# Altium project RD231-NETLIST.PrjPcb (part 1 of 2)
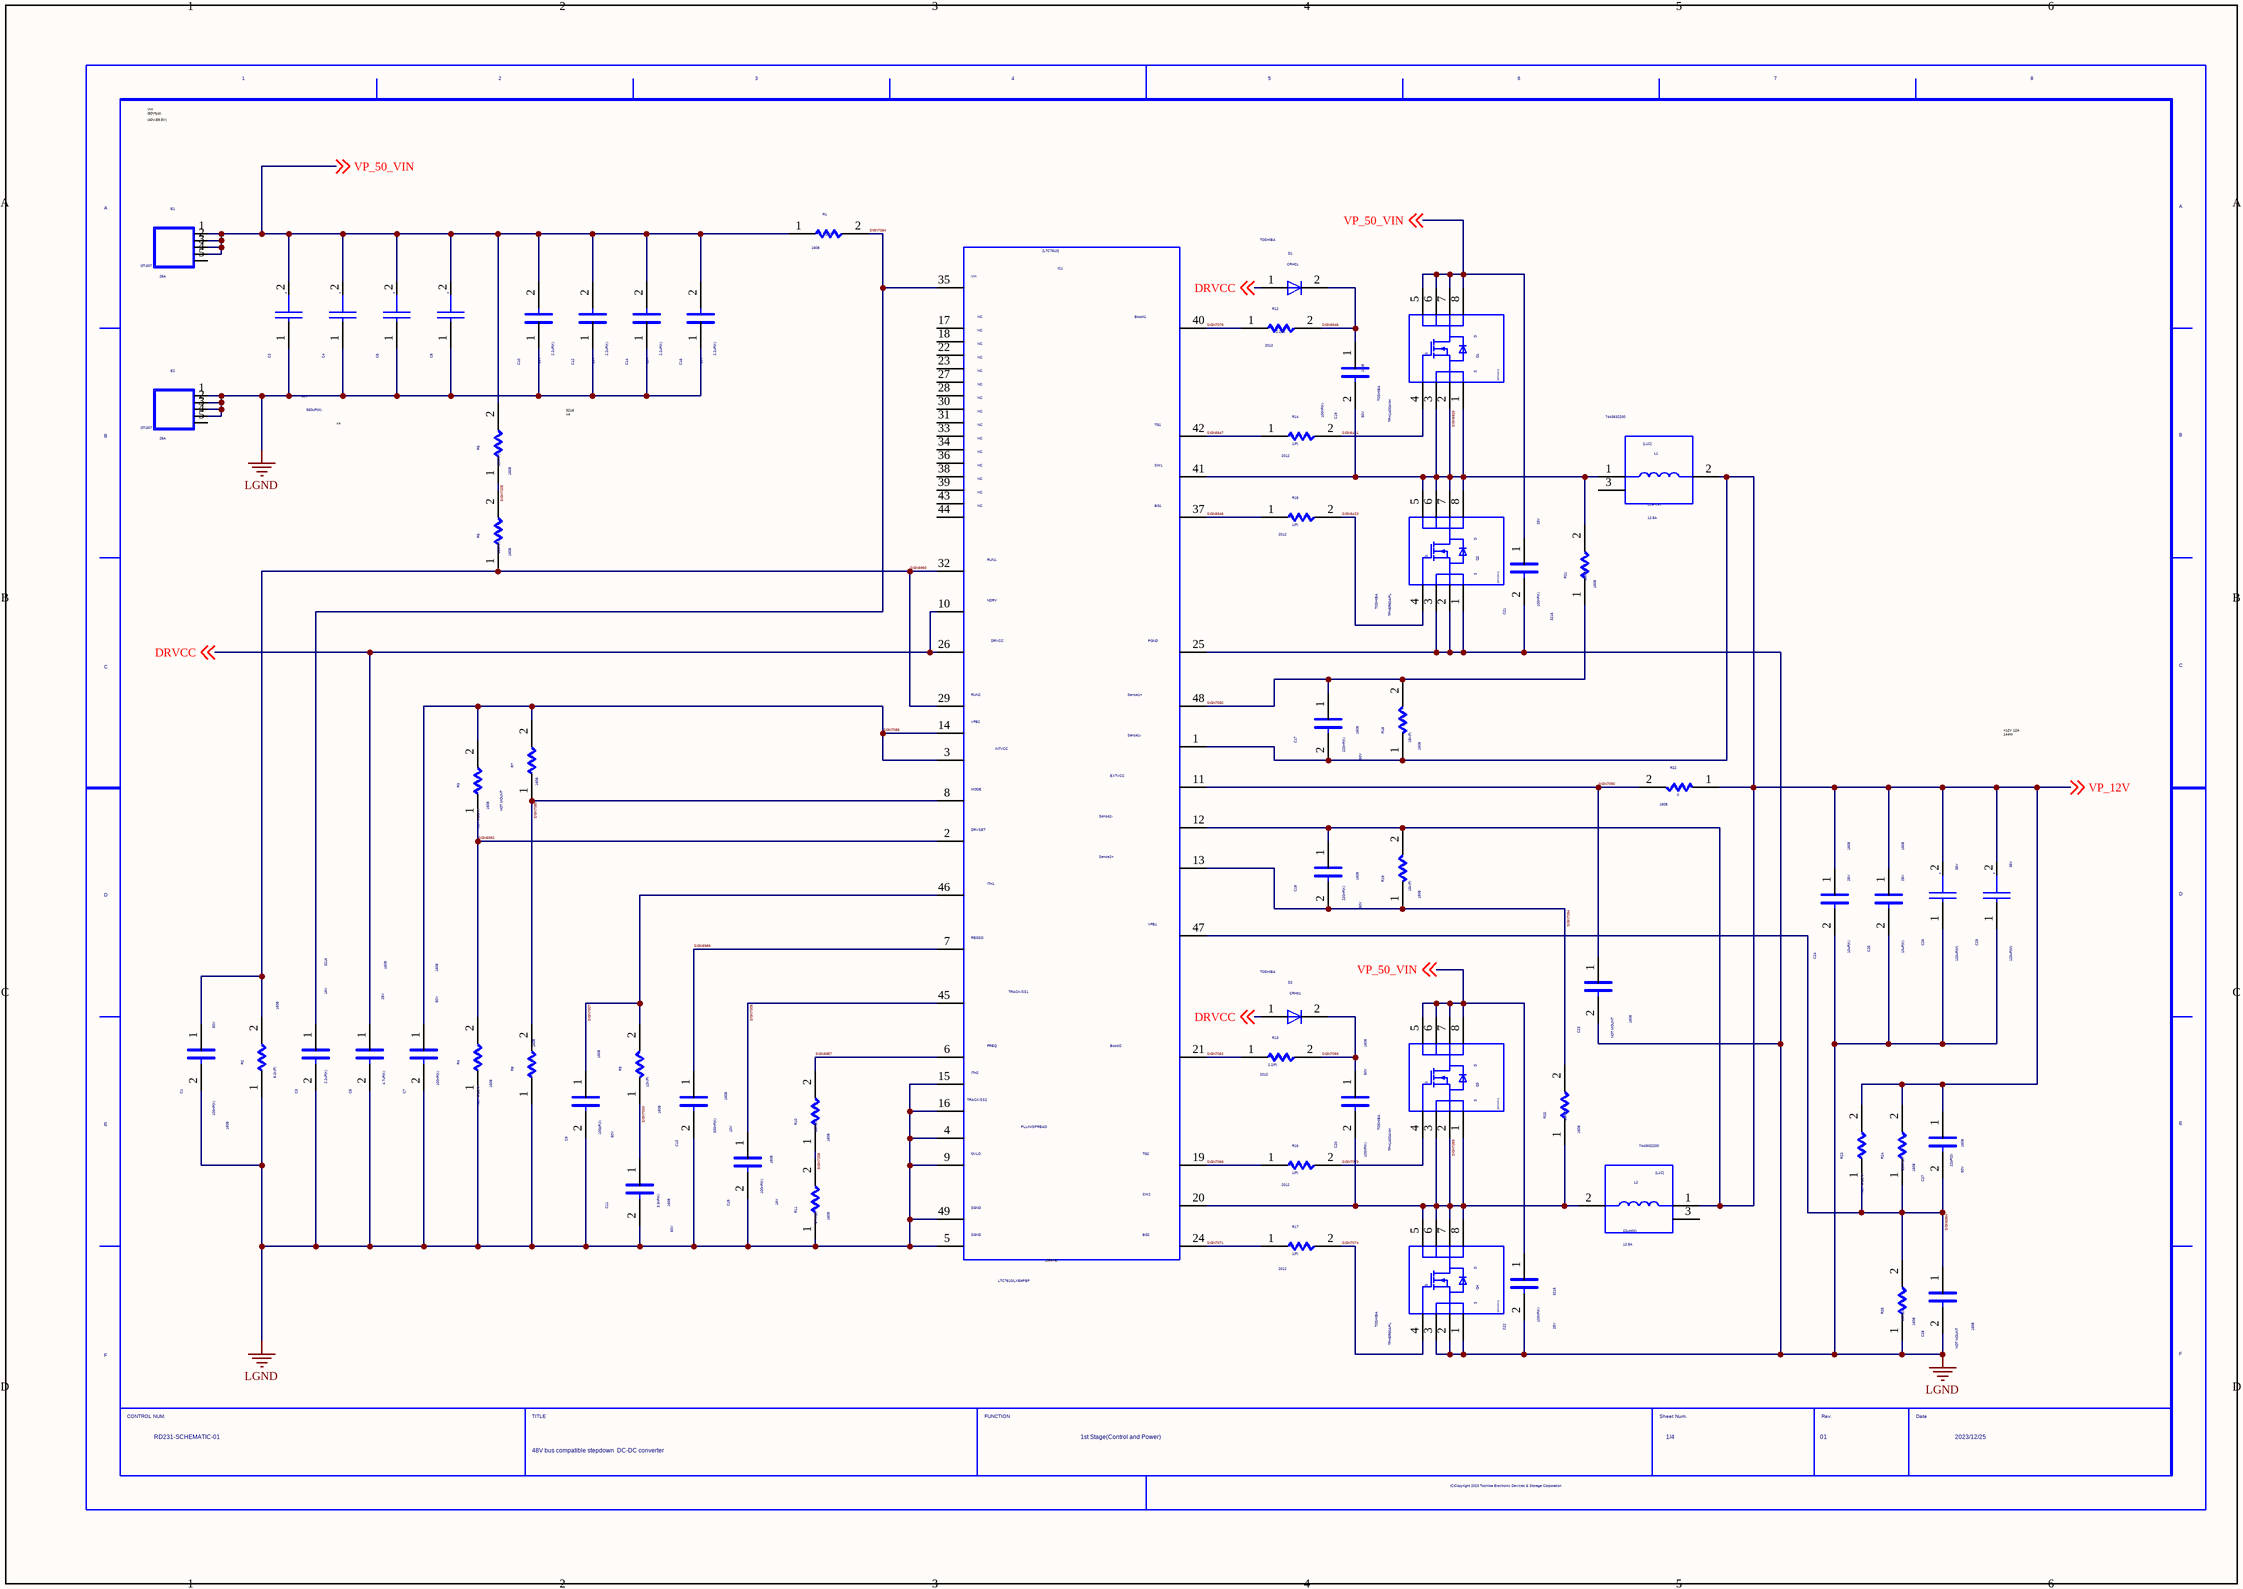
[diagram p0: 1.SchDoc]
4 sheets, 318 parts. Net scope: global (net labels, ports and power ports of the same name join across sheets).
Sheets:
  1.SchDoc
  2.SchDoc
  3.SchDoc
  4.SchDoc

## Sheet 1.SchDoc
size 420 x 297 mm

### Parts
(Parts that share a designator on the sheet are numbered #1, #2 ... from top to bottom, then left to right.)
C1  VAL1: 100nF(K)  VAL2: 50V  SIZECODESMD: 1608  (hidden comment: C)
C2  VAL1: 560uF(M)  VAL2: 80V  (hidden comment: CP)
C3  VAL1: 2.2uF(K)  VAL2: 16V  SIZECODESMD: 3216  (hidden comment: C)
C4  CP  (value not drawn)
C5  VAL1: 4.7uF(K)  VAL2: 25V  SIZECODESMD: 1608  (hidden comment: C)
C6  CP  (value not drawn)
C7  VAL1: 100nF(K)  VAL2: 50V  SIZECODESMD: 1608  (hidden comment: C)
C8  CP  (value not drawn)
C9  VAL1: 100pF(J)  VAL2: 50V  SIZECODESMD: 1608  (hidden comment: C)
C10  VAL1: 2.2uF(K)  VAL2: 16V  (hidden comment: C)
C11  VAL1: 3.3nF(K)  VAL2: 50V  SIZECODESMD: 1608  (hidden comment: C)
C12  VAL1: 2.2uF(K)  VAL2: 16V  (hidden comment: C)
C13  VAL1: 330nF(K)  VAL2: 10V  SIZECODESMD: 1608  (hidden comment: C)
C14  VAL1: 2.2uF(K)  VAL2: 16V  (hidden comment: C)
C15  VAL1: 100nF(K)  VAL2: 16V  SIZECODESMD: 1608  (hidden comment: C)
C16  VAL1: 2.2uF(K)  VAL2: 16V  (hidden comment: C)
C17  VAL1: 220nF(K)  VAL2: 50V  SIZECODESMD: 1608  (hidden comment: C)
C18  VAL1: 220nF(K)  VAL2: 50V  SIZECODESMD: 1608  (hidden comment: C)
C19  VAL1: 100nF(K)  VAL2: 50V  SIZECODESMD: 1608  (hidden comment: C)
C20  VAL1: 100nF(K)  VAL2: 50V  SIZECODESMD: 1608  (hidden comment: C)
C21  VAL1: 100nF(K)  VAL2: 25V  SIZECODESMD: 3216  (hidden comment: C)
C22  VAL1: 100nF(K)  VAL2: 25V  SIZECODESMD: 3216  (hidden comment: C)
C23  SIZECODESMD: 1608  NOTMOUNT: NOT MOUNT  (hidden comment: C)
C24  VAL1: 10uF(K)  VAL2: 25V  SIZECODESMD: 1608  (hidden comment: C)
C25  VAL1: 10uF(K)  VAL2: 25V  SIZECODESMD: 1608  (hidden comment: C)
C26  VAL1: 120uF(M)  VAL2: 35V  (hidden comment: CP)
C27  VAL1: 22pF(D)  VAL2: 50V  SIZECODESMD: 1608  (hidden comment: C)
C28  SIZECODESMD: 1608  NOTMOUNT: NOT MOUNT  (hidden comment: C)
C29  VAL1: 120uF(M)  VAL2: 35V  (hidden comment: CP)
D1  VAL3: CRH01  USERCOMPTEXT3: TOSHIBA  (hidden comment: D)
D2  VAL3: CRH01  USERCOMPTEXT3: TOSHIBA  (hidden comment: D)
E1  VAL1: 25A  VAL3: OT-007  (hidden comment: EB)
E2  VAL1: 25A  VAL3: OT-007  (hidden comment: EB)
IC1  VAL3: LTC7810ILXE#PBF  (hidden comment: LTC7810_1)
L1  VAL1: 22uH(M)  VAL2: 12.5A  VAL3: 7443632200  (hidden comment: L1C)
L2  VAL1: 22uH(M)  VAL2: 12.5A  VAL3: 7443632200  (hidden comment: L1C)
Q1  VAL3: TPH1400ANH  USERCOMPTEXT3: TOSHIBA  (hidden comment: MFNKR2)
Q2  VAL3: TPH5R60APL  USERCOMPTEXT3: TOSHIBA  (hidden comment: MFNKR2)
Q3  VAL3: TPH1400ANH  USERCOMPTEXT3: TOSHIBA  (hidden comment: MFNKR2)
Q4  VAL3: TPH5R60APL  USERCOMPTEXT3: TOSHIBA  (hidden comment: MFNKR2)
R1  VAL1: 2.2(F)  SIZECODESMD: 1608  (hidden comment: R)
R2  VAL1: 8.2k(F)  SIZECODESMD: 1608  (hidden comment: R)
R3  NOTMOUNT: NOT MOUNT  SIZECODESMD: 1608  (hidden comment: R)
R4  NOTMOUNT: NOT MOUNT  SIZECODESMD: 1608  (hidden comment: R)
R5  VAL1: 110k(F)  SIZECODESMD: 1608  (hidden comment: R)
R6  VAL1: 110k(F)  SIZECODESMD: 1608  (hidden comment: R)
R7  SIZECODESMD: 1608  NOTMOUNT: NOT MOUNT  (hidden comment: R)
R8  VAL1: 0  SIZECODESMD: 1608  (hidden comment: R)
R9  VAL1: 12k(F)  SIZECODESMD: 1608  (hidden comment: R)
R10  VAL1: 22k(D)  SIZECODESMD: 1608  (hidden comment: R)
R11  VAL1: 2.7k(D)  SIZECODESMD: 1608  (hidden comment: R)
R12  VAL1: 2.2(F)  SIZECODESMD: 2012  (hidden comment: R)
R13  VAL1: 2.2(F)  SIZECODESMD: 2012  (hidden comment: R)
R14  VAL1: 1(F)  SIZECODESMD: 2012  (hidden comment: R)
R15  VAL1: 1(F)  SIZECODESMD: 2012  (hidden comment: R)
R16  VAL1: 1(F)  SIZECODESMD: 2012  (hidden comment: R)
R17  VAL1: 1(F)  SIZECODESMD: 2012  (hidden comment: R)
R18  VAL1: 15k(F)  SIZECODESMD: 1608  (hidden comment: R)
R19  VAL1: 15k(F)  SIZECODESMD: 1608  (hidden comment: R)
R20  VAL1: 10k(F)  SIZECODESMD: 1608  (hidden comment: R)
R21  VAL1: 10k(F)  SIZECODESMD: 1608  (hidden comment: R)
R22  VAL1: 0  SIZECODESMD: 1608  (hidden comment: R)
R23  NOTMOUNT: NOT MOUNT  (hidden comment: R)
R24  VAL1: 220k(D)  SIZECODESMD: 1608  (hidden comment: R)
R25  VAL1: 20k(D)  SIZECODESMD: 1608  (hidden comment: R)
U?#1  DATE: 2023/12/25  FUNCTION: 1st Stage(Control and Power)  DRAWINGNUMBER: RD231-SCHEMATIC-01  SHEETNUMBER: 1/4  REVISION: 01  TITLE: 48V bus compatible stepdown / DC-DC converter  (hidden comment: WAKU_DEF100)

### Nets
LGND: C1.2 C2.1 C3.2 C4.1 C5.2 C6.1 C7.2 C8.1 C9.2 C10.1 C11.2 C12.1 C13.2 C14.1 C15.2 C16.1 C21.2 C22.2 C23.2 C24.2 C25.2 C26.1 C28.2 C29.1 E2.1 E2.2 E2.3 E2.4 IC1.4 IC1.5 IC1.9 IC1.15 IC1.16 IC1.25 IC1.49 Q2.1 Q2.2 Q2.3 Q4.1 Q4.2 Q4.3 R2.1 R4.1 R8.1 R11.1 R25.1
DRVCC: C5.1 D1.1(A) D2.1(A) IC1.10 IC1.26 ; off-sheet DRVCC
SIGN6423: Q2.4 R15.2
SIGN6441: Q1.4 R14.2
SIGN6926: C19.2 IC1.41 L1.1 Q1.1 Q1.2 Q1.3 Q2.5 Q2.6 Q2.7 Q2.8 R21.2
SIGN6946: IC1.37 R15.1
SIGN6947: IC1.42 R14.1
SIGN6948: C19.1 D1.2(C) R12.2
SIGN6954: C27.2 C28.1 IC1.47 R23.1 R24.1 R25.2
SIGN6957: IC1.6 R10.2
SIGN6960: C1.1 IC1.29 IC1.32 R2.2 R6.1
SIGN6989: C13.1 IC1.7
SIGN6992: IC1.2 R3.1 R4.2
SIGN7000: C11.1 R9.1
SIGN7005: C15.1 IC1.45
SIGN7007: C9.1 IC1.46 R9.2
SIGN7059: C20.2 IC1.20 L2.2 Q3.1 Q3.2 Q3.3 Q4.5 Q4.6 Q4.7 Q4.8 R20.1
SIGN7062: IC1.21 R13.1
SIGN7068: IC1.19 R16.1
SIGN7069: C20.1 D2.2(C) R13.2
SIGN7071: IC1.24 R17.1
SIGN7073: Q3.4 R16.2
SIGN7074: Q4.4 R17.2
SIGN7078: IC1.40 R12.1
SIGN7084: C3.1 IC1.35 R1.2
SIGN7088: C7.1 IC1.3 IC1.14 R3.2 R7.2
SIGN7089: IC1.8 R7.1 R8.2
SIGN7090: C23.1 IC1.11 R22.2
SIGN7092: C17.1 IC1.48 R18.2 R21.1
SIGN7094: C18.2 IC1.13 R19.1 R20.2
SIGN7205: R5.1 R6.2
SIGN7208: R10.1 R11.2
VP_12V: C17.2 C18.1 C24.1 C25.1 C26.2 C27.1 C29.2 IC1.1 IC1.12 L1.2 L2.1 R18.1 R19.2 R22.1 R23.2 R24.2 ; off-sheet VP_12V
VP_50_VIN: C2.2 C4.2 C6.2 C8.2 C10.2 C12.2 C14.2 C16.2 C21.1 C22.1 E1.1 E1.2 E1.3 E1.4 Q1.5 Q1.6 Q1.7 Q1.8 Q3.5 Q3.6 Q3.7 Q3.8 R1.1 R5.2 ; off-sheet VP_50_VIN

Not connected (* = marked no-connect by the designer): E1 5; E2 5; IC1 17 18 22 23 27 28 30 31 33 34 36 38 39 43 44; L1 3; L2 3

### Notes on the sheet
- (40V-59.5V)
- Vin
  (50Vtyp)
- x4
- 3216
  x4
- +12V 12A
  144W
- (near IC1) 100kHz

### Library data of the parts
C1 C7 C19 C20 C23 = C: PARTCOMMENT: 代表セル<KC0008> がフットプリントに登録されていません。; FNPARTSNAMEG: CHIP CERAMIC CAPACITOR (1608); OriginalSymbolOrigin: (2540,7620); FNCLASSCODEG: P03-03; PCODE: P03B000001KW; USEWITHSCHEMA: YES; MFMOUNTSYMBOLP: 80; FUNCN: GDM030001005; MFFORMINGDIVP: KC; MFPACKAGEMETHOP: S; MFSOLDERINGPROP: .; COMPONENTNAME: GDM030001005_package; GCOUNT: 1
C2 C26 C29 = CP: FNPARTSCODEG: C; FNPARTSNAMEG: CHIP ALUMINUM ELECTROLYTIC CAPACITOR; SAVEAREA0: -1450,-153,20294,13055; SAVECOUNT: 52; TIME: 15:02:55; UPDATEUSER: fukuda-y; UPDATETIME: 16:13:42; OriginalSymbolOrigin: (2540,10160); USEWITHSCHEMA: YES; FUNCN: G36030155199; GCOUNT: 1; COMPONENTNAME: G36030155199_package; FNCLASSCODEG: P03-01; PCODE: P03090017118; MFMOUNTSYMBOLP: 80; MFFORMINGDIVP: KD; MFPACKAGEMETHOP: S; MFSOLDERINGPROP: F
C3 = C: FNPARTSNAMEG: CHIP CERAMIC CAPACITOR (3216); OriginalSymbolOrigin: (2540,7620); FNCLASSCODEG: P03-03; PCODE: P03042997321; USEWITHSCHEMA: YES; MFMOUNTSYMBOLP: 90; FUNCN: G36030110013; MFFORMINGDIVP: KC; MFPACKAGEMETHOP: S; MFSOLDERINGPROP: .; COMPONENTNAME: G36030110013_package; GCOUNT: 1; TOLERANCE: K
C4 C6 C8 = CP: FNPARTSCODEG: C; FNPARTSNAMEG: CHIP ALUMINUM ELECTROLYTIC CAPACITOR; SAVEAREA0: -1450,-153,20294,13055; SAVECOUNT: 52; TIME: 15:02:55; UPDATEUSER: fukuda-y; UPDATETIME: 16:13:42; OriginalSymbolOrigin: (2540,10160); USEWITHSCHEMA: YES; FUNCN: G36030155199; GCOUNT: 1; COMPONENTNAME: G36030155199_package; VAL1: 560uF(M); VAL2: 80V; FNCLASSCODEG: P03-01; PCODE: P03090017118; MFMOUNTSYMBOLP: 80; MFFORMINGDIVP: KD; MFPACKAGEMETHOP: S; MFSOLDERINGPROP: F
C5 = C: PARTCOMMENT: 代表セル<KC0008> がフットプリントに登録されていません。; FNPARTSNAMEG: CHIP CERAMIC CAPACITOR (1608); OriginalSymbolOrigin: (2540,7620); FNCLASSCODEG: P03-03; PCODE: P03B000001NY; USEWITHSCHEMA: YES; MFMOUNTSYMBOLP: 80; FUNCN: GDM030001182; MFFORMINGDIVP: KC; MFPACKAGEMETHOP: S; MFSOLDERINGPROP: .; COMPONENTNAME: GDM030001182_package; GCOUNT: 1
C9 = C: FNPARTSNAMEG: CHIP CERAMIC CAPACITOR (1608); OriginalSymbolOrigin: (2540,7620); FNCLASSCODEG: P03-03; PCODE: P03039307126; USEWITHSCHEMA: YES; MFMOUNTSYMBOLP: 80; FUNCN: G36030011181; MFFORMINGDIVP: KC; MFPACKAGEMETHOP: S; MFSOLDERINGPROP: .; COMPONENTNAME: G36030011181_package; GCOUNT: 1; TOLERANCE: J
C10 C12 C14 C16 = C: FNPARTSNAMEG: CHIP CERAMIC CAPACITOR (3216); OriginalSymbolOrigin: (2540,7620); FNCLASSCODEG: P03-03; USEWITHSCHEMA: YES; FUNCN: G36030110013; SIZECODESMD: 3216; COMPONENTNAME: G36030110013_package; GCOUNT: 1; PCODE: P03042997321; MFMOUNTSYMBOLP: 90; MFFORMINGDIVP: KC; MFPACKAGEMETHOP: S; MFSOLDERINGPROP: .; TOLERANCE: K
C11 = C: FNPARTSNAMEG: CHIP CERAMIC CAPACITOR (1608); OriginalSymbolOrigin: (2540,7620); FNCLASSCODEG: P03-03; PCODE: P03039A11122; USEWITHSCHEMA: YES; MFMOUNTSYMBOLP: 80; FUNCN: G36030011075; MFFORMINGDIVP: KC; MFPACKAGEMETHOP: S; MFSOLDERINGPROP: .; COMPONENTNAME: G36030011075_package; GCOUNT: 1; TOLERANCE: K
C13 = C: FNPARTSNAMEG: CHIP CERAMIC CAPACITOR (1608); OriginalSymbolOrigin: (2540,7620); FNCLASSCODEG: P03-03; PCODE: P03039ABF120; USEWITHSCHEMA: YES; MFMOUNTSYMBOLP: 80; FUNCN: G36030104111; MFFORMINGDIVP: KC; MFPACKAGEMETHOP: S; MFSOLDERINGPROP: .; COMPONENTNAME: G36030104111_package; GCOUNT: 1
C15 = C: FNPARTSNAMEG: CHIP CERAMIC CAPACITOR (1608); OriginalSymbolOrigin: (2540,7620); FNCLASSCODEG: P03-03; PCODE: P03039996139; USEWITHSCHEMA: YES; MFMOUNTSYMBOLP: 80; FUNCN: G36030011419; MFFORMINGDIVP: KC; MFPACKAGEMETHOP: S; MFSOLDERINGPROP: .; COMPONENTNAME: G36030011419_package; GCOUNT: 1
C17 C18 = C: FNPARTSNAMEG: CHIP CERAMIC CAPACITOR (1608); OriginalSymbolOrigin: (2540,7620); FNCLASSCODEG: P03-03; PCODE: P03039ABG127; USEWITHSCHEMA: YES; MFMOUNTSYMBOLP: 80; FUNCN: G36030104128; MFFORMINGDIVP: KC; MFPACKAGEMETHOP: S; MFSOLDERINGPROP: .; COMPONENTNAME: G36030104128_package; GCOUNT: 1
C21 C22 = C: FNPARTSNAMEG: CHIP CERAMIC CAPACITOR (3216); OriginalSymbolOrigin: (2540,7620); FNCLASSCODEG: P03-03; PCODE: P03042006320; USEWITHSCHEMA: YES; MFMOUNTSYMBOLP: 90; FUNCN: G36030031080; MFFORMINGDIVP: KC; MFPACKAGEMETHOP: S; MFSOLDERINGPROP: .; COMPONENTNAME: G36030031080_package; GCOUNT: 1; TOLERANCE: K
C24 C25 = C: FNPARTSNAMEG: CHIP CERAMIC CAPACITOR (1608); OriginalSymbolOrigin: (2540,7620); FNCLASSCODEG: P03-03; PCODE: P03B000000MS; USEWITHSCHEMA: YES; MFMOUNTSYMBOLP: 80; FUNCN: GDM030000053; MFFORMINGDIVP: KC; MFPACKAGEMETHOP: S; MFSOLDERINGPROP: .; COMPONENTNAME: GDM030000053_package; GCOUNT: 1
C27 C28 = C: FNPARTSNAMEG: CHIP CERAMIC CAPACITOR (1608); OriginalSymbolOrigin: (2540,7620); FNCLASSCODEG: P03-03; PCODE: P03039185229; USEWITHSCHEMA: YES; MFMOUNTSYMBOLP: 80; FUNCN: G36030011013; MFFORMINGDIVP: KC; MFPACKAGEMETHOP: S; MFSOLDERINGPROP: .; COMPONENTNAME: G36030011013_package; GCOUNT: 1; TOLERANCE: D
D1 D2 = D: SAVEAREA0: -565,-171,12979,8058; SAVECOUNT: 3; TIME: 14:49:55; UPDATEUSER: 19870035; UPDATETIME: 14:20:16; OriginalSymbolOrigin: (5080,5080); USEWITHSCHEMA: YES; VAL1: 1A; OUMEMAKERKATAMEI: CMF02(TE12R,Q); COMP: 5P9L1110P002; OUMEMAKER: 東芝; VAL2: 200V
E1 E2 = EB: SAVEAREA0: -10166,-6669,19798,9727; TIME: 17:33:04; UPDATEUSER: sptcae13; SAVECOUNT: 1; OriginalSymbolOrigin: (0,8890); COMP: 5P9L1232P001
IC1 = LTC7810_1: TIME: 17:42:33; UPDATEUSER: q91873sr; UPDATETIME: 00:58:17; SAVECOUNT: 171; SAVEAREA0: -56936,59772,124648,157086; OriginalSymbolOrigin: (5080,193040); USEWITHSCHEMA: YES; COMPONENTNAME: LTC7810_1.LTC7810_1; GCOUNT: 1
L1 L2 = L1C: SAVECOUNT: 6; SAVEAREA0: -5636,-341,27978,18652; OriginalSymbolOrigin: (5080,15240); USEWITHSCHEMA: YES; OUMEMAKERKATAMEI: 7443630140; GCOUNT: 1; OUMEMAKER: WURTH; COMPONENTNAME: L1C_L1C
Q1-Q4 = MFNKR2: SAVEAREA0: -9199,-39,32138,22820; TIME: 18:57:44; UPDATEUSER: q91866sr; UPDATETIME: 12:36:02; SAVECOUNT: 10; OriginalSymbolOrigin: (5080,20320); USEWITHSCHEMA: YES; OUMEMAKERKATAMEI: TPH6R003NL; COMPONENTNAME: MFNKR2_MFNKR2; GCOUNT: 1
R1 = R: FNPARTSNAMEG: CHIP RESISTOR (1608); OriginalSymbolOrigin: (5080,5080); FNCLASSCODEG: P01-08; PCODE: P01183001112; USEWITHSCHEMA: YES; VAL2: 100mW; NUMBEROFELEMENT: 0; COMP: G36010141013; MFFORMINGDIVP: KC; MFPACKAGEMETHOP: S; MFSOLDERINGPROP: .; MFMOUNTSYMBOLP: 80; COMPONENTNAME: G36010141013_package
R2 = R: FNPARTSNAMEG: CHIP RESISTOR (1608); OriginalSymbolOrigin: (5080,5080); FNCLASSCODEG: P01-08; PCODE: P01042507328; USEWITHSCHEMA: YES; VAL2: 100mW; NUMBEROFELEMENT: 0; COMP: G36010027188; MFFORMINGDIVP: KC; MFPACKAGEMETHOP: S; MFSOLDERINGPROP: .; MFMOUNTSYMBOLP: 80; COMPONENTNAME: G36010027188_package; GCOUNT: 1; TOLERANCE: F
R3 R4 = R: FNPARTSNAMEG: CHIP RESISTOR (1608); OriginalSymbolOrigin: (5080,5080); FNCLASSCODEG: P01-08; PCODE: P01042049A26; USEWITHSCHEMA: YES; NUMBEROFELEMENT: 0; COMP: G36010027034; MFFORMINGDIVP: KC; MFPACKAGEMETHOP: S; MFSOLDERINGPROP: .; MFMOUNTSYMBOLP: 80; COMPONENTNAME: G36010027034_package; GCOUNT: 1; TOLERANCE: F
R5 R6 = R: FNPARTSNAMEG: CHIP RESISTOR (1608); OriginalSymbolOrigin: (5080,5080); FNCLASSCODEG: P01-08; PCODE: P01042519628; USEWITHSCHEMA: YES; VAL2: 100mW; NUMBEROFELEMENT: 0; COMP: G36010027300; MFFORMINGDIVP: KC; MFPACKAGEMETHOP: S; MFSOLDERINGPROP: .; MFMOUNTSYMBOLP: 80; COMPONENTNAME: G36010027300_package; GCOUNT: 1; TOLERANCE: F
R7 = R: FNPARTSNAMEG: CHIP RESISTOR (1608); OriginalSymbolOrigin: (5080,5080); FNCLASSCODEG: P01-08; PCODE: P01042045226; USEWITHSCHEMA: YES; NUMBEROFELEMENT: 0; COMP: G36010027133; MFFORMINGDIVP: KC; MFPACKAGEMETHOP: S; MFSOLDERINGPROP: .; MFMOUNTSYMBOLP: 80; COMPONENTNAME: G36010027133_package; GCOUNT: 1; TOLERANCE: F
R8 = R: FNPARTSNAMEG: CHIP RESISTOR (1608); OriginalSymbolOrigin: (5080,5080); FNCLASSCODEG: P01-08; PCODE: P01042207426; USEWITHSCHEMA: YES; COMP: G36010027089; MFFORMINGDIVP: KC; MFPACKAGEMETHOP: S; MFSOLDERINGPROP: .; MFMOUNTSYMBOLP: 80; COMPONENTNAME: G36010027089_package; GCOUNT: 1; TOLERANCE: F
R9 = R: FNPARTSNAMEG: CHIP RESISTOR (1608); OriginalSymbolOrigin: (5080,5080); FNCLASSCODEG: P01-08; USEWITHSCHEMA: YES; VAL2: 100mW; COMP: G36010027041; PCODE: P01042097423; NUMBEROFELEMENT: 0; MFMOUNTSYMBOLP: 80; MFFORMINGDIVP: KC; MFPACKAGEMETHOP: S; MFSOLDERINGPROP: .; TOLERANCE: F; COMPONENTNAME: G36010027041_package; GCOUNT: 1
R10 = R: FNPARTSNAMEG: CHIP RESISTOR (1608); OriginalSymbolOrigin: (5080,5080); FNCLASSCODEG: P01-08; USEWITHSCHEMA: YES; VAL2: 62.5mW; COMP: G36010129578; PCODE: P01119059118; NUMBEROFELEMENT: 0; MFMOUNTSYMBOLP: 80; MFFORMINGDIVP: KC; MFPACKAGEMETHOP: S; MFSOLDERINGPROP: .; COMPONENTNAME: G36010129578_package; GCOUNT: 1
R11 = R: FNPARTSNAMEG: CHIP RESISTOR (1608); OriginalSymbolOrigin: (5080,5080); FNCLASSCODEG: P01-08; USEWITHSCHEMA: YES; VAL2: 62.5mW; COMP: G36010129356; PCODE: P01117039112; NUMBEROFELEMENT: 0; MFMOUNTSYMBOLP: 80; MFFORMINGDIVP: KC; MFPACKAGEMETHOP: S; MFSOLDERINGPROP: .; COMPONENTNAME: G36010129356_package; GCOUNT: 1
R12 R13 = R: FNPARTSNAMEG: CHIP RESISTOR (2012); OriginalSymbolOrigin: (5080,5080); FNCLASSCODEG: P01-08; PCODE: P01048019214; USEWITHSCHEMA: YES; VAL2: 125mW; NUMBEROFELEMENT: 0; MFMOUNTSYMBOLP: 90; FUNCN: G36010106012; MFFORMINGDIVP: KC; MFPACKAGEMETHOP: S; MFSOLDERINGPROP: .; COMPONENTNAME: G36010106012_package; GCOUNT: 1
R14-R17 = R: FNPARTSNAMEG: CHIP RESISTOR (2012); OriginalSymbolOrigin: (5080,5080); FNCLASSCODEG: P01-08; PCODE: P01048017210; USEWITHSCHEMA: YES; VAL2: 125mW; NUMBEROFELEMENT: 0; MFMOUNTSYMBOLP: 90; FUNCN: G36010106081; MFFORMINGDIVP: KC; MFPACKAGEMETHOP: S; MFSOLDERINGPROP: .; COMPONENTNAME: G36010106081_package; GCOUNT: 1
R18 R19 = R: FNPARTSNAMEG: CHIP RESISTOR (1608); OriginalSymbolOrigin: (5080,5080); FNCLASSCODEG: P01-08; USEWITHSCHEMA: YES; VAL2: 100mW; COMP: G36010027058; PCODE: P01042113727; NUMBEROFELEMENT: 0; MFMOUNTSYMBOLP: 80; MFFORMINGDIVP: KC; MFPACKAGEMETHOP: S; MFSOLDERINGPROP: .; TOLERANCE: F; COMPONENTNAME: G36010027058_package; GCOUNT: 1
R20 R21 = R: FNPARTSNAMEG: CHIP RESISTOR (1608); OriginalSymbolOrigin: (5080,5080); FNCLASSCODEG: P01-08; USEWITHSCHEMA: YES; VAL2: 100mW; COMP: G5101105R107; PCODE: P01042424625; NUMBEROFELEMENT: 0; MFMOUNTSYMBOLP: 80; MFFORMINGDIVP: KC; MFPACKAGEMETHOP: S; MFSOLDERINGPROP: .; COMPONENTNAME: G5101105R107_package; GCOUNT: 1
R22 = R: PARTCOMMENT: 代表セル<KC0008> がフットプリントに登録されていません。; FNPARTSNAMEG: CHIP JUMPER 1608TYPE; OriginalSymbolOrigin: (5080,5080); FNCLASSCODEG: P01-08; USEWITHSCHEMA: YES; FUNCN: K0100346; COMPONENTNAME: K0100346_package; GCOUNT: 1
R23 = R: FNPARTSNAMEG: CHIP RESISTOR (1608); OriginalSymbolOrigin: (5080,5080); FNCLASSCODEG: P01-08; USEWITHSCHEMA: YES; COMP: G5101106F106; PCODE: P01042680229; NUMBEROFELEMENT: 0; MFMOUNTSYMBOLP: 80; MFFORMINGDIVP: KC; MFPACKAGEMETHOP: S; MFSOLDERINGPROP: .; COMPONENTNAME: G5101106F106_package; GCOUNT: 1; SIZECODESMD: 1608
R24 = R: FNPARTSNAMEG: CHIP RESISTOR (1608); OriginalSymbolOrigin: (5080,5080); FNCLASSCODEG: P01-08; USEWITHSCHEMA: YES; VAL2: 62.5mW; COMP: G5101109J104; PCODE: P01042669620; NUMBEROFELEMENT: 0; MFMOUNTSYMBOLP: 80; MFFORMINGDIVP: KC; MFPACKAGEMETHOP: S; MFSOLDERINGPROP: .; COMPONENTNAME: G5101109J104_package; GCOUNT: 1
R25 = R: FNPARTSNAMEG: CHIP RESISTOR (1608); OriginalSymbolOrigin: (5080,5080); FNCLASSCODEG: P01-08; USEWITHSCHEMA: YES; VAL2: 62.5mW; COMP: G36010129493; PCODE: P01117053118; NUMBEROFELEMENT: 0; MFMOUNTSYMBOLP: 80; MFFORMINGDIVP: KC; MFPACKAGEMETHOP: S; MFSOLDERINGPROP: .; COMPONENTNAME: G36010129493_package; GCOUNT: 1
U?#1 = WAKU_DEF100: PLOTTIME: HH:MM; SAVEAREA0: -56280,0,471144,298016; TIME: 20:22:11; UPDATEUSER: sptcae13; UPDATETIME: 11:34:32; SAVECOUNT: 8; OriginalSymbolOrigin: (10160,284480)

## Sheet 2.SchDoc
size 420 x 297 mm
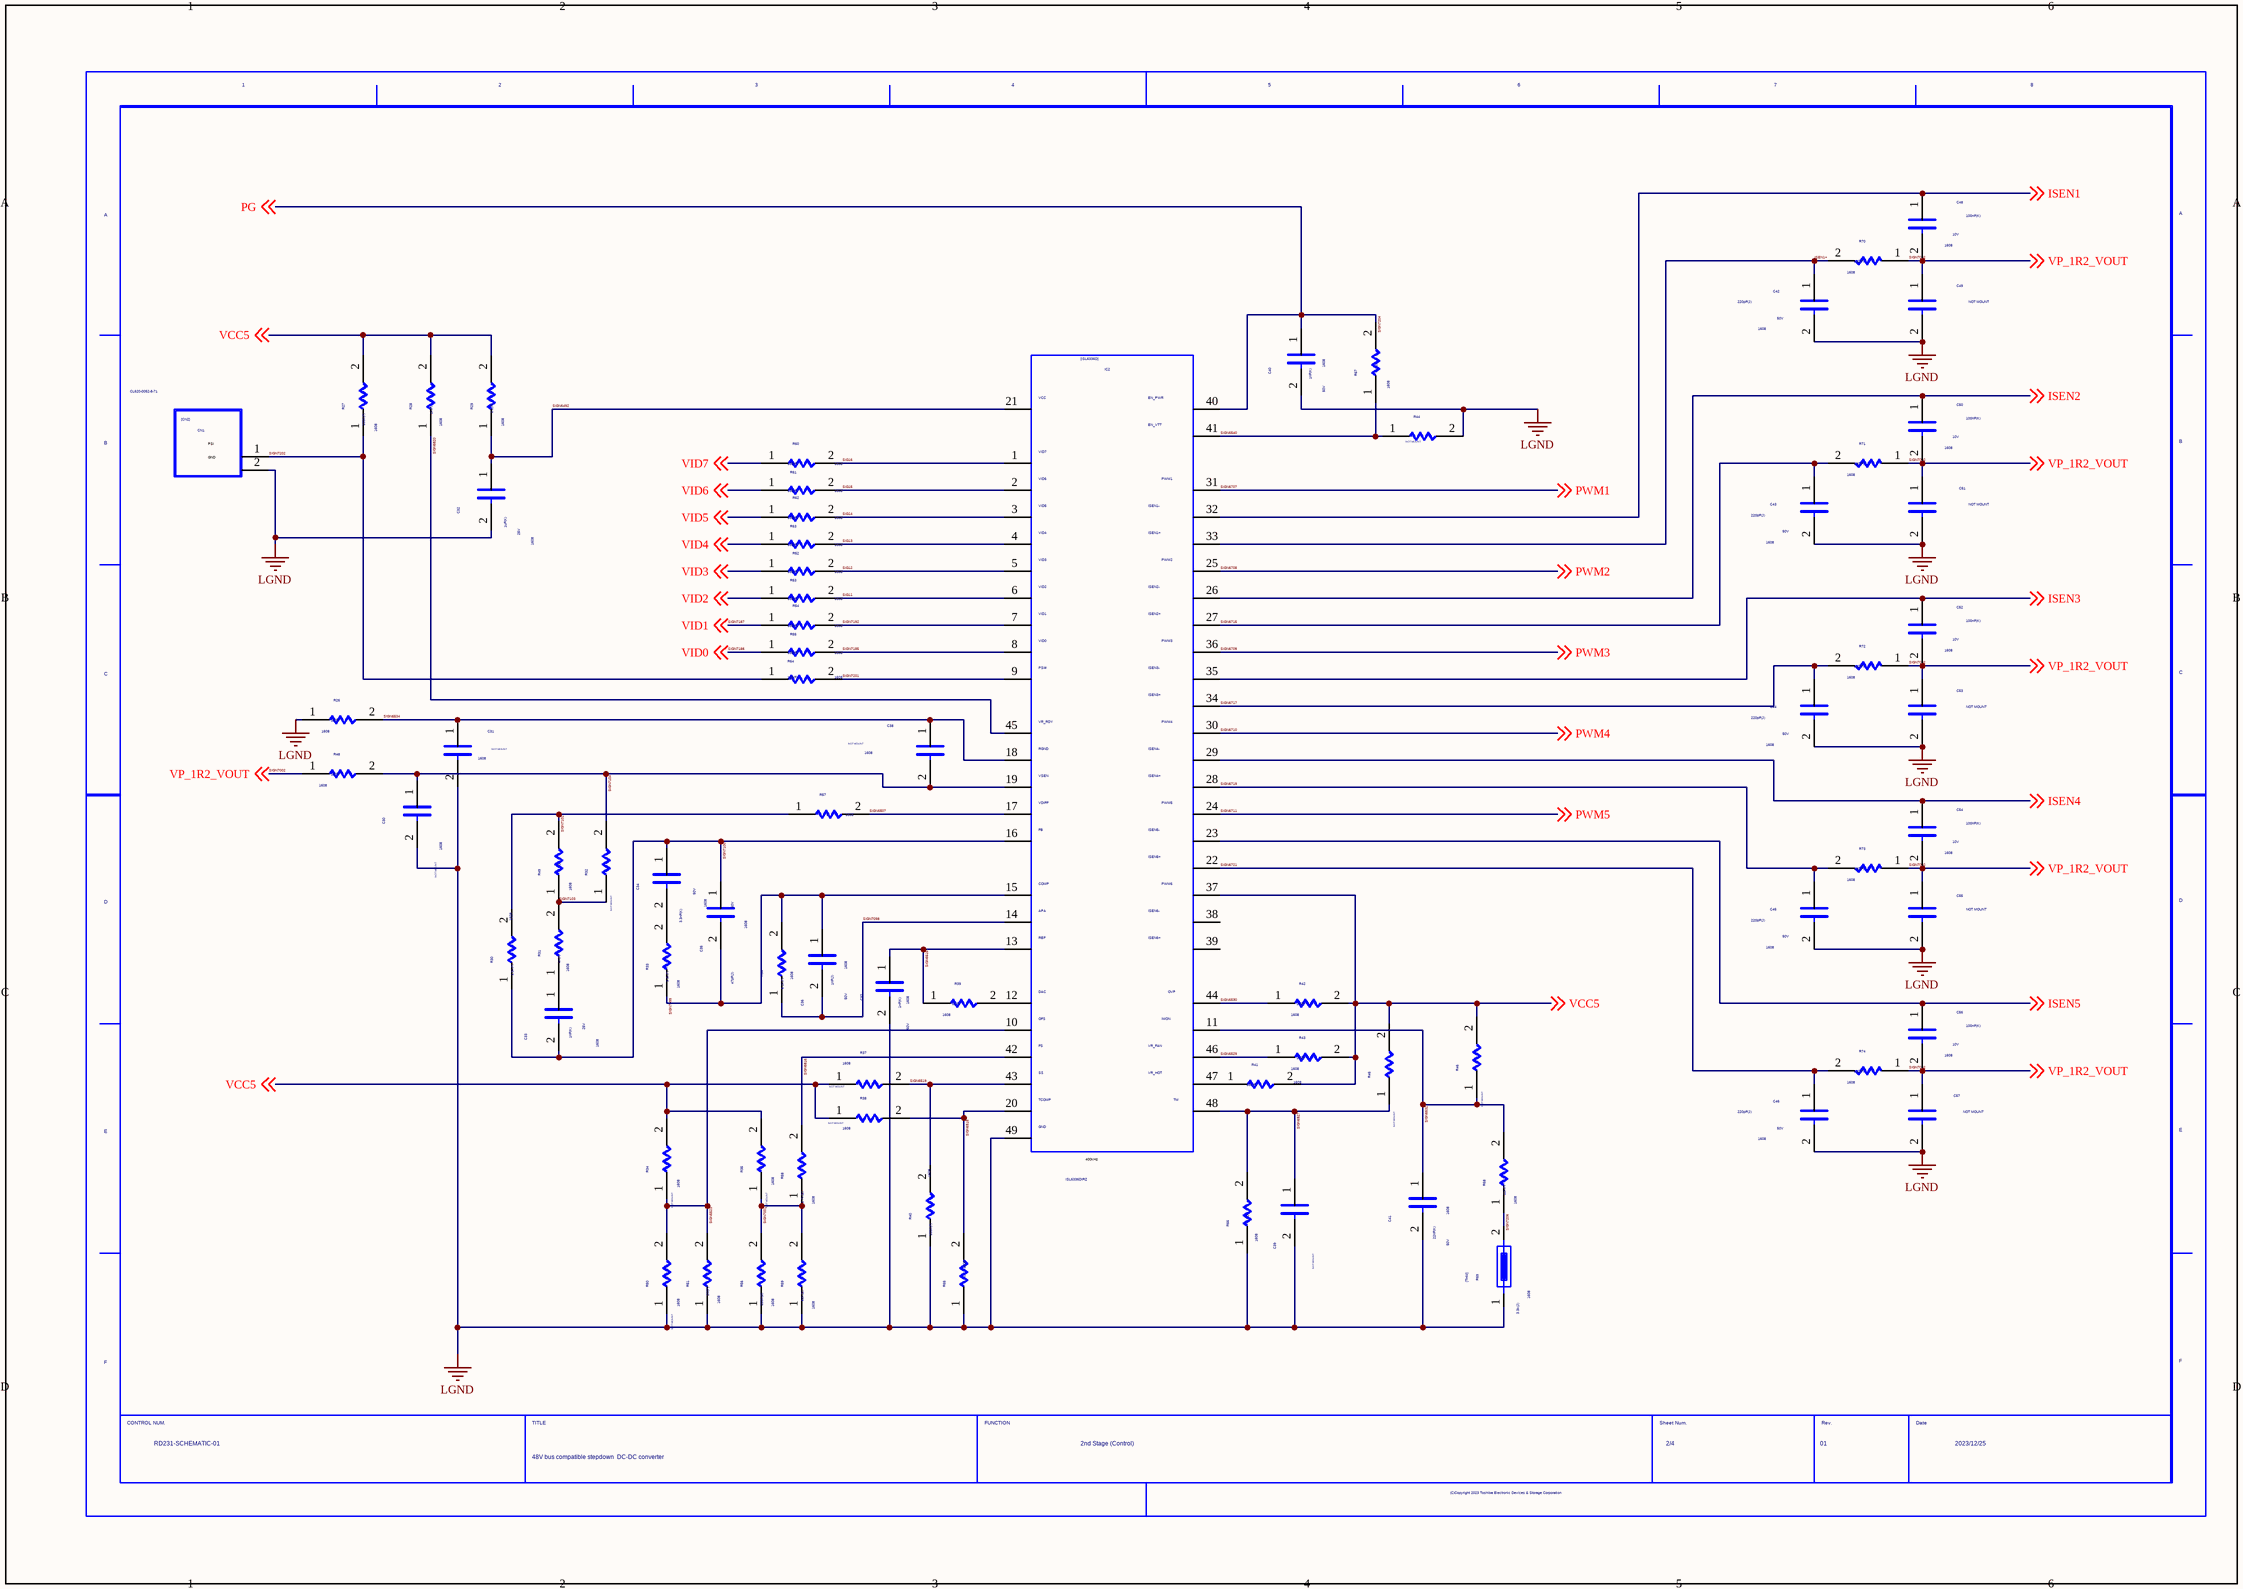
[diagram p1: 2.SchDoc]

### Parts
(Parts that share a designator on the sheet are numbered #1, #2 ... from top to bottom, then left to right.)
C30  NOTMOUNT: NOT MOUNT  SIZECODESMD: 1608  (hidden comment: C)
C31  NOTMOUNT: NOT MOUNT  SIZECODESMD: 1608  (hidden comment: C)
C32  SIZECODESMD: 1608  VAL2: 25V  VAL1: 1uF(K)  (hidden comment: C)
C33  SIZECODESMD: 1608  VAL2: 25V  VAL1: 1nF(K)  (hidden comment: C)
C34  SIZECODESMD: 1608  VAL2: 50V  VAL1: 3.3nF(K)  (hidden comment: C)
C35  SIZECODESMD: 1608  VAL2: 50V  VAL1: 47pF(J)  (hidden comment: C)
C36  SIZECODESMD: 1608  VAL2: 50V  VAL1: 1nF(J)  (hidden comment: C)
C37  SIZECODESMD: 1608  VAL2: 50V  VAL1: 1nF(K)  (hidden comment: C)
C38  NOTMOUNT: NOT MOUNT  SIZECODESMD: 1608  (hidden comment: C)
C39  NOTMOUNT: NOT MOUNT  (hidden comment: C)
C40  SIZECODESMD: 1608  VAL2: 50V  VAL1: 1nF(K)  (hidden comment: C)
C41  SIZECODESMD: 1608  VAL2: 50V  VAL1: 22nF(K)  (hidden comment: C)
C42  SIZECODESMD: 1608  VAL2: 50V  VAL1: 220pF(J)  (hidden comment: C)
C43  SIZECODESMD: 1608  VAL2: 50V  VAL1: 220pF(J)  (hidden comment: C)
C44  SIZECODESMD: 1608  VAL2: 50V  VAL1: 220pF(J)  (hidden comment: C)
C45  SIZECODESMD: 1608  VAL2: 50V  VAL1: 220pF(J)  (hidden comment: C)
C46  SIZECODESMD: 1608  VAL2: 50V  VAL1: 220pF(J)  (hidden comment: C)
C48  SIZECODESMD: 1608  VAL2: 10V  VAL1: 100nF(K)  (hidden comment: C)
C49  NOTMOUNT: NOT MOUNT  (hidden comment: C)
C50  SIZECODESMD: 1608  VAL2: 10V  VAL1: 100nF(K)  (hidden comment: C)
C51  NOTMOUNT: NOT MOUNT  (hidden comment: C)
C52  SIZECODESMD: 1608  VAL2: 10V  VAL1: 100nF(K)  (hidden comment: C)
C53  NOTMOUNT: NOT MOUNT  (hidden comment: C)
C54  SIZECODESMD: 1608  VAL2: 10V  VAL1: 100nF(K)  (hidden comment: C)
C55  NOTMOUNT: NOT MOUNT  (hidden comment: C)
C56  SIZECODESMD: 1608  VAL2: 10V  VAL1: 100nF(K)  (hidden comment: C)
C57  NOTMOUNT: NOT MOUNT  (hidden comment: C)
CN1  VAL3: CL620-0052-8-71  (hidden comment: CN2)
IC2  VAL3: ISL6336DIRZ  (hidden comment: ISL6336D)
R26  SIZECODESMD: 1608  VAL1: 10(F)  (hidden comment: R)
R27  SIZECODESMD: 1608  VAL1: 100k(F)  (hidden comment: R)
R28  SIZECODESMD: 1608  VAL1: 1k(F)  (hidden comment: R)
R29  SIZECODESMD: 1608  VAL1: 2.2(F)  (hidden comment: R)
R30  SIZECODESMD: 1608  VAL1: 1.5k(F)  (hidden comment: R)
R31  SIZECODESMD: 1608  VAL1: 47(F)  (hidden comment: R)
R32  NOTMOUNT: NOT MOUNT  (hidden comment: R)
R33  SIZECODESMD: 1608  VAL1: 3.3k(F)  (hidden comment: R)
R34  SIZECODESMD: 1608  NOTMOUNT: NOT MOUNT  (hidden comment: R)
R35  SIZECODESMD: 1608  NOTMOUNT: NOT MOUNT  (hidden comment: R)
R36  SIZECODESMD: 1608  VAL1: 8.2k(F)  (hidden comment: R)
R37  SIZECODESMD: 1608  NOTMOUNT: NOT MOUNT  (hidden comment: R)
R38  SIZECODESMD: 1608  NOTMOUNT: NOT MOUNT  (hidden comment: R)
R39  SIZECODESMD: 1608  VAL1: 1k(F)  (hidden comment: R)
R40  SIZECODESMD: 1608  VAL1: 100k(F)  (hidden comment: R)
R41  SIZECODESMD: 1608  VAL1: 10k(F)  (hidden comment: R)
R42  SIZECODESMD: 1608  VAL1: 1k(F)  (hidden comment: R)
R43  SIZECODESMD: 1608  VAL1: 1k(F)  (hidden comment: R)
R44  NOTMOUNT: NOT MOUNT  (hidden comment: R)
R45  NOTMOUNT: NOT MOUNT  (hidden comment: R)
R46  NOTMOUNT: NOT MOUNT  (hidden comment: R)
R48  SIZECODESMD: 1608  VAL1: 10(F)  (hidden comment: R)
R49  SIZECODESMD: 1608  VAL1: 0  (hidden comment: R)
R50  SIZECODESMD: 1608  NOTMOUNT: NOT MOUNT  (hidden comment: R)
R51  SIZECODESMD: 1608  VAL1: 1M(F)  (hidden comment: R)
R52  SIZECODESMD: 1608  VAL1: 100(F)  (hidden comment: R)
R53  SIZECODESMD: 1608  VAL1: 100(F)  (hidden comment: R)
R54  SIZECODESMD: 1608  VAL1: 100(F)  (hidden comment: R)
R55  SIZECODESMD: 1608  VAL1: 100(F)  (hidden comment: R)
R56  SIZECODESMD: 1608  VAL1: 220k(D)  (hidden comment: R)
R57  SIZECODESMD: 1608  VAL1: 0  (hidden comment: R)
R58  SIZECODESMD: 1608  VAL1: 2.7k(D)  (hidden comment: R)
R59  SIZECODESMD: 1608  VAL1: 82k(D)  (hidden comment: R)
R60  SIZECODESMD: 1608  VAL1: 100(F)  (hidden comment: R)
R61  SIZECODESMD: 1608  VAL1: 100(F)  (hidden comment: R)
R62  SIZECODESMD: 1608  VAL1: 100(F)  (hidden comment: R)
R63  SIZECODESMD: 1608  VAL1: 100(F)  (hidden comment: R)
R64  SIZECODESMD: 1608  VAL1: 100(F)  (hidden comment: R)
R65  SIZECODESMD: 1608  VAL1: 0  (hidden comment: R)
R66  SIZECODESMD: 1608  VAL1: 0  (hidden comment: R)
R67  SIZECODESMD: 1608  VAL1: 0  (hidden comment: R)
R68  SIZECODESMD: 1608  VAL1: 11k(F)  (hidden comment: R)
R69  SIZECODESMD: 1608  VAL1: 3.3k(J)  (hidden comment: THM)
R70  SIZECODESMD: 1608  VAL1: 130(F)  (hidden comment: R)
R71  SIZECODESMD: 1608  VAL1: 130(F)  (hidden comment: R)
R72  SIZECODESMD: 1608  VAL1: 130(F)  (hidden comment: R)
R73  SIZECODESMD: 1608  VAL1: 130(F)  (hidden comment: R)
R74  SIZECODESMD: 1608  VAL1: 130(F)  (hidden comment: R)
U?#2  DATE: 2023/12/25  TITLE: 48V bus compatible stepdown / DC-DC converter  REVISION: 01  SHEETNUMBER: 2/4  DRAWINGNUMBER: RD231-SCHEMATIC-01  FUNCTION: 2nd Stage (Control)  (hidden comment: WAKU_DEF100)

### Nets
LGND: C30.2 C31.2 C32.2 C37.2 C39.2 C40.2 C41.2 C42.2 C43.2 C44.2 C45.2 C46.2 C49.2 C51.2 C53.2 C55.2 C57.2 CN1.2 IC2.49 R26.1 R40.1 R44.2 R50.1 R51.1 R56.1 R59.1 R65.1 R66.1 R69.1
ISEN1: C48.1 IC2.32 ; off-sheet ISEN1
ISEN1+: C42.1 IC2.33 R70.2
ISEN2: C50.1 IC2.26 ; off-sheet ISEN2
ISEN3: C52.1 IC2.35 ; off-sheet ISEN3
ISEN4: C54.1 IC2.29 ; off-sheet ISEN4
ISEN5: C56.1 IC2.23 ; off-sheet ISEN5
SIG11: IC2.6 R53.2
SIG12: IC2.5 R52.2
SIG13: IC2.4 R63.2
SIG14: IC2.3 R62.2
SIG15: IC2.2 R61.2
SIG16: IC2.1 R60.2
SIGN6492: C32.1 IC2.21 R29.1
SIGN6507: IC2.17 R57.2
SIGN6515: C37.1 IC2.13 R39.1
SIGN6516: IC2.20 R38.2 R65.2
SIGN6519: IC2.43 R37.2 R40.2
SIGN6523: IC2.10 R34.1 R50.2 R51.2
SIGN6527: C39.1 IC2.48 R45.1 R66.2
SIGN6529: IC2.46 R43.1
SIGN6530: IC2.44 R42.1
SIGN6532: C41.1 IC2.11 R46.1 R68.2
SIGN6534: C31.1 C38.1 IC2.18 R26.2
SIGN6540: IC2.41 R44.1 R67.1
SIGN6707: IC2.31 ; off-sheet PWM1  [also labelled PWM1]
SIGN6708: IC2.25 ; off-sheet PWM2  [also labelled PWM2]
SIGN6709: IC2.36 ; off-sheet PWM3  [also labelled PWM3]
SIGN6710: IC2.30 ; off-sheet PWM4  [also labelled PWM4]
SIGN6711: IC2.24 ; off-sheet PWM5  [also labelled PWM5]
SIGN6715: C43.1 IC2.27 R71.2
SIGN6717: C44.1 IC2.34 R72.2
SIGN6719: C45.1 IC2.28 R73.2
SIGN6721: C46.1 IC2.22 R74.2
SIGN6816: IC2.42 R58.2
SIGN6820: IC2.45 R28.1
SIGN7001: R35.1 R56.2 R58.1 R59.2
SIGN7002: C48.2 C49.1 C50.2 C51.1 C52.2 C53.1 C54.2 C55.1 C56.2 C57.1 R48.1 R70.1 R71.1 R72.1 R73.1 R74.1 ; off-sheet VP_1R2_VOUT  [also labelled VP_1R2_VOUT]
SIGN7098: C36.2 IC2.14 R36.1
SIGN7099: C35.2 C36.1 IC2.15 R33.1 R36.2
SIGN7100: C33.2 C34.1 C35.1 IC2.16 R30.1
SIGN7102: R30.2 R49.2 R57.1
SIGN7103: R31.2 R32.1 R49.1
SIGN7104: C30.1 C38.2 IC2.19 R32.2 R48.2
SIGN7185: IC2.8 R55.2
SIGN7186: R55.1 ; off-sheet VID0  [also labelled VID0]
SIGN7187: R54.1 ; off-sheet VID1  [also labelled VID1]
SIGN7192: IC2.7 R54.2
SIGN7201: IC2.9 R64.2
SIGN7202: CN1.1 R27.1 R64.1
SIGN7204: C40.1 IC2.40 R67.2 ; off-sheet PG  [also labelled PG]
SIGN7206: R68.1 R69.2
VCC5: IC2.37 R27.2 R28.2 R29.2 R34.2 R35.2 R37.1 R38.1 R41.2 R42.2 R43.2 R45.2 R46.2 ; off-sheet VCC5
VID2: R53.1 ; off-sheet VID2
VID3: R52.1 ; off-sheet VID3
VID4: R63.1 ; off-sheet VID4
VID5: R62.1 ; off-sheet VID5
VID6: R61.1 ; off-sheet VID6
VID7: R60.1 ; off-sheet VID7
NetC33_1: C33.1 R31.1
NetC34_2: C34.2 R33.2
NetIC2_12: IC2.12 R39.2
NetIC2_47: IC2.47 R41.1

Not connected (* = marked no-connect by the designer): IC2 38 39

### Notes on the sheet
- (near CN1) PSI
- (near CN1) GND
- (near IC2) 400kHz

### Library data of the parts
C30 C31 C38 = C: FNPARTSNAMEG: CHIP CERAMIC CAPACITOR (1608); USEINPARTSLIST: YES; OriginalSymbolOrigin: (2540,7620); TOLERANCE: K; MAXGCOUNT: 1; COMPONENTNAME: G36030011310_package; MFSOLDERINGPROP: .; MFPACKAGEMETHOP: S; MFFORMINGDIVP: KC; COMP: G36030011310; MFMOUNTSYMBOLP: 80; PCODE: P03039AAN526; FNCLASSCODEG: P03-03
C32 = C: FNPARTSNAMEG: CHIP CERAMIC CAPACITOR (1608); USEINPARTSLIST: YES; OriginalSymbolOrigin: (2540,7620); MAXGCOUNT: 1; COMPONENTNAME: G36030011433_package; MFSOLDERINGPROP: .; MFPACKAGEMETHOP: S; MFFORMINGDIVP: KC; COMP: G36030011433; MFMOUNTSYMBOLP: 80; PCODE: P03039992230; FNCLASSCODEG: P03-03
C33 = C: FNPARTSNAMEG: CHIP CERAMIC CAPACITOR (1608); USEINPARTSLIST: YES; OriginalSymbolOrigin: (2540,7620); TOLERANCE: K; MAXGCOUNT: 1; COMPONENTNAME: G36030011297_package; MFSOLDERINGPROP: .; MFPACKAGEMETHOP: S; MFFORMINGDIVP: KC; COMP: G36030011297; MFMOUNTSYMBOLP: 80; PCODE: P03039008221; FNCLASSCODEG: P03-03
C34 = C: FNPARTSNAMEG: CHIP CERAMIC CAPACITOR (1608); USEINPARTSLIST: YES; OriginalSymbolOrigin: (2540,7620); TOLERANCE: K; MAXGCOUNT: 1; COMPONENTNAME: G36030011037_package; MFSOLDERINGPROP: .; MFPACKAGEMETHOP: S; MFFORMINGDIVP: KC; COMP: G36030011037; MFMOUNTSYMBOLP: 80; PCODE: P03039A0T125; FNCLASSCODEG: P03-03
C35 = C: FNPARTSNAMEG: CHIP CERAMIC CAPACITOR (1608); USEINPARTSLIST: YES; OriginalSymbolOrigin: (2540,7620); TOLERANCE: K; MAXGCOUNT: 1; COMPONENTNAME: G36030011303_package; MFSOLDERINGPROP: .; MFPACKAGEMETHOP: S; MFFORMINGDIVP: KC; COMP: G36030011303; MFMOUNTSYMBOLP: 80; PCODE: P03039A0P127; FNCLASSCODEG: P03-03
C36 = C: FNPARTSNAMEG: CHIP CERAMIC CAPACITOR (1608); USEINPARTSLIST: YES; OriginalSymbolOrigin: (2540,7620); MAXGCOUNT: 1; COMPONENTNAME: G36030011747_package; MFSOLDERINGPROP: .; MFPACKAGEMETHOP: S; MFFORMINGDIVP: KC; COMP: G36030011747; MFMOUNTSYMBOLP: 80; PCODE: P03190012112; FNCLASSCODEG: P03-03
C37 C40 = C: FNPARTSNAMEG: CHIP CERAMIC CAPACITOR (1608); USEINPARTSLIST: YES; OriginalSymbolOrigin: (2540,7620); TOLERANCE: K; MAXGCOUNT: 1; COMPONENTNAME: G36030011044_package; MFSOLDERINGPROP: .; MFPACKAGEMETHOP: S; MFFORMINGDIVP: KC; COMP: G36030011044; MFMOUNTSYMBOLP: 80; PCODE: P03039045226; FNCLASSCODEG: P03-03
C39 = C: FNPARTSNAMEG: CHIP CERAMIC CAPACITOR (1608); USEINPARTSLIST: YES; OriginalSymbolOrigin: (2540,7620); TOLERANCE: K; MAXGCOUNT: 1; COMPONENTNAME: G36030011310_package; MFSOLDERINGPROP: .; MFPACKAGEMETHOP: S; MFFORMINGDIVP: KC; COMP: G36030011310; SIZECODESMD: 1608; MFMOUNTSYMBOLP: 80; PCODE: P03039AAN526; FNCLASSCODEG: P03-03
C41 = C: FNPARTSNAMEG: CHIP CERAMIC CAPACITOR (1608); USEINPARTSLIST: YES; OriginalSymbolOrigin: (2540,7620); TOLERANCE: K; PCODE: P03039008221; MAXGCOUNT: 1; COMPONENTNAME: G36030011297_package; MFSOLDERINGPROP: .; MFPACKAGEMETHOP: S; MFFORMINGDIVP: KC; COMP: G36030011297; MFMOUNTSYMBOLP: 80; FNCLASSCODEG: P03-03
C42-C46 = C: FNPARTSNAMEG: CHIP CERAMIC CAPACITOR (1608); USEINPARTSLIST: YES; OriginalSymbolOrigin: (2540,7620); MAXGCOUNT: 1; COMPONENTNAME: G36030011488_package; MFSOLDERINGPROP: .; MFPACKAGEMETHOP: S; MFFORMINGDIVP: KC; COMP: G36030011488; MFMOUNTSYMBOLP: 80; PCODE: P03039269127; FNCLASSCODEG: P03-03
C48 C50 C52 C54 C56 = C: FNPARTSNAMEG: CHIP CERAMIC CAPACITOR (1608); USEINPARTSLIST: YES; OriginalSymbolOrigin: (2540,7620); MAXGCOUNT: 1; COMPONENTNAME: GDM030000714_package; MFSOLDERINGPROP: .; MFPACKAGEMETHOP: S; MFFORMINGDIVP: KC; COMP: GDM030000714; MFMOUNTSYMBOLP: 80; PCODE: P03039ABE123; FNCLASSCODEG: P03-03
C49 C51 C53 C55 C57 = C: FNPARTSNAMEG: CHIP CERAMIC CAPACITOR (1608); USEINPARTSLIST: YES; OriginalSymbolOrigin: (2540,7620); MAXGCOUNT: 1; COMPONENTNAME: G36030104128_package; MFSOLDERINGPROP: .; MFPACKAGEMETHOP: S; MFFORMINGDIVP: KC; COMP: G36030104128; SIZECODESMD: 1608; MFMOUNTSYMBOLP: 80; PCODE: P03039ABG127; FNCLASSCODEG: P03-03
CN1 = CN2: USEINPARTSLIST: YES; OUMEPARTTYPE: PJ; OriginalSymbolOrigin: (2540,15240); MAXGCOUNT: 1; COMPONENTNAME: ZS_DPJ028_package; QUADMODEL: dummymodel; COMP: ZS_DPJ028
IC2 = ISL6336D: USEINPARTSLIST: YES; TIME: 17:42:33; UPDATEUSER: q91866sr; UPDATETIME: 10:56:10; SAVECOUNT: 140; SAVEAREA0: -131159,-2851,167371,162238; OriginalSymbolOrigin: (5080,152400); MAXGCOUNT: 1; COMPONENTNAME: ISL6336D.ISL6336D; OUMEMAKER: Renesas
R26 = R: FNPARTSNAMEG: CHIP RESISTOR (1608); USEINPARTSLIST: YES; OriginalSymbolOrigin: (5080,5080); COMPONENTNAME: G36010104063_package; FUNCN: G36010104063; TOLERANCE: F; MFSOLDERINGPROP: .; MFPACKAGEMETHOP: S; MFFORMINGDIVP: KC; MFMOUNTSYMBOLP: 80; NUMBEROFELEMENT: 0; PCODE: P01042036620; VAL2: 100mW; FNCLASSCODEG: P01-08
R27 = R: FNPARTSNAMEG: CHIP RESISTOR (1608); USEINPARTSLIST: YES; OriginalSymbolOrigin: (5080,5080); COMPONENTNAME: G36010027133_package; FUNCN: G36010027133; TOLERANCE: F; MFSOLDERINGPROP: .; MFPACKAGEMETHOP: S; MFFORMINGDIVP: KC; MFMOUNTSYMBOLP: 80; NUMBEROFELEMENT: 0; VAL2: 100mW; PCODE: P01042045226; FNCLASSCODEG: P01-08
R28 = R: FNPARTSNAMEG: CHIP RESISTOR (1608); USEINPARTSLIST: YES; OriginalSymbolOrigin: (5080,5080); MAXGCOUNT: 1; COMPONENTNAME: G36010027324_package; FUNCN: G36010027324; TOLERANCE: F; MFSOLDERINGPROP: .; MFPACKAGEMETHOP: S; MFFORMINGDIVP: KC; MFMOUNTSYMBOLP: 80; NUMBEROFELEMENT: 0; VAL2: 100mW; PCODE: P01042521225; FNCLASSCODEG: P01-08
R29 = R: FNPARTSNAMEG: CHIP RESISTOR (1608); USEINPARTSLIST: YES; OriginalSymbolOrigin: (5080,5080); COMPONENTNAME: G36010141013_package; FUNCN: G36010141013; MFMOUNTSYMBOLP: 80; MFSOLDERINGPROP: .; MFPACKAGEMETHOP: S; MFFORMINGDIVP: KC; NUMBEROFELEMENT: 0; VAL2: 100mW; PCODE: P01183001112; FNCLASSCODEG: P01-08
R30 = R: FNPARTSNAMEG: CHIP RESISTOR (1608); USEINPARTSLIST: YES; OriginalSymbolOrigin: (5080,5080); COMPONENTNAME: G36010104339_package; FUNCN: G36010104339; MFSOLDERINGPROP: .; MFPACKAGEMETHOP: S; MFFORMINGDIVP: KC; MFMOUNTSYMBOLP: 80; NUMBEROFELEMENT: 0; PCODE: P01042159428; VAL2: 100mW; FNCLASSCODEG: P01-08
R31 = R: FNPARTSNAMEG: CHIP JUMPER 1608TYPE; USEINPARTSLIST: YES; PARTCOMMENT: 代表セル<KC0008> がフットプリントに登録されていません。; OriginalSymbolOrigin: (5080,5080); MAXGCOUNT: 1; COMPONENTNAME: K0100346_package; FUNCN: K0100346; VAL2: 100mW; FNCLASSCODEG: P01-08
R32 R44 = R: FNPARTSNAMEG: CHIP RESISTOR (1608); USEINPARTSLIST: YES; OriginalSymbolOrigin: (5080,5080); SIZECODESMD: 1608; COMPONENTNAME: G36010129400_package; FUNCN: G36010129400; PCODE: P01117044116; MFSOLDERINGPROP: .; MFPACKAGEMETHOP: S; MFFORMINGDIVP: KC; MFMOUNTSYMBOLP: 80; NUMBEROFELEMENT: 0; FNCLASSCODEG: P01-08
R33 = R: FNPARTSNAMEG: CHIP RESISTOR (1608); USEINPARTSLIST: YES; OriginalSymbolOrigin: (5080,5080); MAXGCOUNT: 1; COMPONENTNAME: G36010104353_package; FUNCN: G36010104353; MFSOLDERINGPROP: .; MFPACKAGEMETHOP: S; MFFORMINGDIVP: KC; MFMOUNTSYMBOLP: 80; NUMBEROFELEMENT: 0; PCODE: P01042007620; VAL2: 100mW; FNCLASSCODEG: P01-08
R34 R35 R37 = R: FNPARTSNAMEG: CHIP RESISTOR (1608); USEINPARTSLIST: YES; OriginalSymbolOrigin: (5080,5080); COMPONENTNAME: G36010129400_package; FUNCN: G36010129400; PCODE: P01117044116; MFSOLDERINGPROP: .; MFPACKAGEMETHOP: S; MFFORMINGDIVP: KC; MFMOUNTSYMBOLP: 80; NUMBEROFELEMENT: 0; FNCLASSCODEG: P01-08
R36 = R: FNPARTSNAMEG: CHIP RESISTOR (1608); USEINPARTSLIST: YES; OriginalSymbolOrigin: (5080,5080); COMPONENTNAME: G36010027188_package; FUNCN: G36010027188; TOLERANCE: F; MFSOLDERINGPROP: .; MFPACKAGEMETHOP: S; MFFORMINGDIVP: KC; MFMOUNTSYMBOLP: 80; NUMBEROFELEMENT: 0; PCODE: P01042507328; VAL2: 100mW; FNCLASSCODEG: P01-08
R38 = R: FNPARTSNAMEG: CHIP RESISTOR (1608); USEINPARTSLIST: YES; OriginalSymbolOrigin: (5080,5080); COMPONENTNAME: G36010027034_package; FUNCN: G36010027034; TOLERANCE: F; MFSOLDERINGPROP: .; MFPACKAGEMETHOP: S; MFFORMINGDIVP: KC; MFMOUNTSYMBOLP: 80; NUMBEROFELEMENT: 0; PCODE: P01042049A26; FNCLASSCODEG: P01-08
R39 R42 R43 = R: FNPARTSNAMEG: CHIP RESISTOR (1608); USEINPARTSLIST: YES; OriginalSymbolOrigin: (5080,5080); COMPONENTNAME: G36010027324_package; FUNCN: G36010027324; TOLERANCE: F; MFSOLDERINGPROP: .; MFPACKAGEMETHOP: S; MFFORMINGDIVP: KC; MFMOUNTSYMBOLP: 80; NUMBEROFELEMENT: 0; PCODE: P01042521225; VAL2: 100mW; FNCLASSCODEG: P01-08
R40 = R: FNPARTSNAMEG: CHIP RESISTOR (1608); USEINPARTSLIST: YES; OriginalSymbolOrigin: (5080,5080); COMPONENTNAME: G36010027133_package; FUNCN: G36010027133; TOLERANCE: F; MFSOLDERINGPROP: .; MFPACKAGEMETHOP: S; MFFORMINGDIVP: KC; MFMOUNTSYMBOLP: 80; NUMBEROFELEMENT: 0; PCODE: P01042045226; VAL2: 100mW; FNCLASSCODEG: P01-08
R41 = R: FNPARTSNAMEG: CHIP RESISTOR (1608); USEINPARTSLIST: YES; OriginalSymbolOrigin: (5080,5080); COMPONENTNAME: G36010027034_package; FUNCN: G36010027034; TOLERANCE: F; MFSOLDERINGPROP: .; MFPACKAGEMETHOP: S; MFFORMINGDIVP: KC; MFMOUNTSYMBOLP: 80; NUMBEROFELEMENT: 0; PCODE: P01042049A26; VAL2: 100mW; FNCLASSCODEG: P01-08
R45 = R: FNPARTSNAMEG: CHIP RESISTOR (1608); USEINPARTSLIST: YES; OriginalSymbolOrigin: (5080,5080); SIZECODESMD: 1608; COMPONENTNAME: G36010027324_package; FUNCN: G36010027324; TOLERANCE: F; MFSOLDERINGPROP: .; MFPACKAGEMETHOP: S; MFFORMINGDIVP: KC; MFMOUNTSYMBOLP: 80; NUMBEROFELEMENT: 0; PCODE: P01042521225; FNCLASSCODEG: P01-08
R46 = R: FNPARTSNAMEG: CHIP RESISTOR (1608); USEINPARTSLIST: YES; OriginalSymbolOrigin: (5080,5080); SIZECODESMD: 1608; COMPONENTNAME: G5101106E109_package; FUNCN: G5101106E109; MFSOLDERINGPROP: .; MFPACKAGEMETHOP: S; MFFORMINGDIVP: KC; MFMOUNTSYMBOLP: 80; NUMBEROFELEMENT: 0; PCODE: P01042153228; FNCLASSCODEG: P01-08
R48 = R: FNPARTSNAMEG: CHIP RESISTOR (1608); USEINPARTSLIST: YES; OriginalSymbolOrigin: (5080,5080); MAXGCOUNT: 1; COMPONENTNAME: G36010104063_package; FUNCN: G36010104063; TOLERANCE: F; MFSOLDERINGPROP: .; MFPACKAGEMETHOP: S; MFFORMINGDIVP: KC; MFMOUNTSYMBOLP: 80; NUMBEROFELEMENT: 0; PCODE: P01042036620; VAL2: 100mW; FNCLASSCODEG: P01-08
R49 R57 R65-R67 = R: FNPARTSNAMEG: CHIP JUMPER 1608TYPE; USEINPARTSLIST: YES; PARTCOMMENT: 代表セル<KC0008> がフットプリントに登録されていません。; OriginalSymbolOrigin: (5080,5080); MAXGCOUNT: 1; COMPONENTNAME: K0100346_package; FUNCN: K0100346; FNCLASSCODEG: P01-08
R50 = R: FNPARTSNAMEG: CHIP RESISTOR (1608); USEINPARTSLIST: YES; OriginalSymbolOrigin: (5080,5080); MAXGCOUNT: 1; COMPONENTNAME: G36010129639_package; FUNCN: G36010129639; MFSOLDERINGPROP: .; MFPACKAGEMETHOP: S; MFFORMINGDIVP: KC; MFMOUNTSYMBOLP: 80; NUMBEROFELEMENT: 0; PCODE: P01117067115; FNCLASSCODEG: P01-08
R51 = R: FNPARTSNAMEG: CHIP RESISTOR (1608); USEINPARTSLIST: YES; OriginalSymbolOrigin: (5080,5080); MAXGCOUNT: 1; COMPONENTNAME: G5101106E109_package; FUNCN: G5101106E109; MFSOLDERINGPROP: .; MFPACKAGEMETHOP: S; MFFORMINGDIVP: KC; MFMOUNTSYMBOLP: 80; NUMBEROFELEMENT: 0; PCODE: P01042153228; VAL2: 100mW; FNCLASSCODEG: P01-08
R52-R55 R60-R64 = R: FNPARTSNAMEG: CHIP RESISTOR (1608); USEINPARTSLIST: YES; OriginalSymbolOrigin: (5080,5080); MAXGCOUNT: 1; COMPONENTNAME: G36010104087_package; FUNCN: G36010104087; TOLERANCE: F; MFSOLDERINGPROP: .; MFPACKAGEMETHOP: S; MFFORMINGDIVP: KC; MFMOUNTSYMBOLP: 80; NUMBEROFELEMENT: 0; PCODE: P01042041426; VAL2: 100mW; FNCLASSCODEG: P01-08
R56 = R: FNPARTSNAMEG: CHIP RESISTOR (1608); USEINPARTSLIST: YES; OriginalSymbolOrigin: (5080,5080); MAXGCOUNT: 1; COMPONENTNAME: G36010014355_package; FUNCN: G36010014355; MFSOLDERINGPROP: .; MFPACKAGEMETHOP: S; MFFORMINGDIVP: KC; MFMOUNTSYMBOLP: 80; NUMBEROFELEMENT: 0; PCODE: P01042201820; VAL2: 62.5mW; FNCLASSCODEG: P01-08
R58 = R: FNPARTSNAMEG: CHIP RESISTOR (1608); USEINPARTSLIST: YES; OriginalSymbolOrigin: (5080,5080); MFSOLDERINGPROP: .; MFPACKAGEMETHOP: S; MFFORMINGDIVP: KC; MFMOUNTSYMBOLP: 80; NUMBEROFELEMENT: 0; PCODE: P01117039112; MAXGCOUNT: 1; COMPONENTNAME: G36010129356_package; FUNCN: G36010129356; VAL2: 62.5mW; FNCLASSCODEG: P01-08
R59 = R: FNPARTSNAMEG: CHIP RESISTOR (1608); USEINPARTSLIST: YES; OriginalSymbolOrigin: (5080,5080); MAXGCOUNT: 1; COMPONENTNAME: G36010129714_package; FUNCN: G36010129714; MFSOLDERINGPROP: .; MFPACKAGEMETHOP: S; MFFORMINGDIVP: KC; MFMOUNTSYMBOLP: 80; NUMBEROFELEMENT: 0; PCODE: P01117075110; VAL2: 62.5mW; FNCLASSCODEG: P01-08
R68 = R: FNPARTSNAMEG: CHIP RESISTOR (1608); USEINPARTSLIST: YES; OriginalSymbolOrigin: (5080,5080); MAXGCOUNT: 1; COMPONENTNAME: G36010027164_package; FUNCN: G36010027164; TOLERANCE: F; MFSOLDERINGPROP: .; MFPACKAGEMETHOP: S; MFFORMINGDIVP: KC; MFMOUNTSYMBOLP: 80; NUMBEROFELEMENT: 0; PCODE: P01042066221; VAL2: 100mW; FNCLASSCODEG: P01-08
R69 = THM: FNPARTSNAMEG: CHIP NTC THERMISTOR; USEINPARTSLIST: YES; OUMEPARTTYPE: MT; PARTCOMMENT: 代表セル<KC0008> がフットプリントに登録されていません。; SAVECOUNT: 4; SAVEAREA0: -824,-117,15885,10433; TIME: 16:37:29; UPDATEUSER: tomizawa-y; UPDATETIME: 10:51:47; OriginalSymbolOrigin: (2540,5080); DCSPARKOVERVOLT: 0.000000000000000; COMPONENTNAME: K0900027_package; MAXGCOUNT: 1; MFSOLDERINGPROP: .; MFPACKAGEMETHOP: S; MFFORMINGDIVP: KC; COMP: K0900027; MFMOUNTSYMBOLP: 80; VARISTORVOLTAGE: 0; VAL2: 100mW; FNCLASSCODEG: P09-01
R70-R74 = R: FNPARTSNAMEG: CHIP RESISTOR (1608); USEINPARTSLIST: YES; OriginalSymbolOrigin: (5080,5080); MAXGCOUNT: 1; COMPONENTNAME: G5101104N107_package; FUNCN: G5101104N107; MFSOLDERINGPROP: .; MFPACKAGEMETHOP: S; MFFORMINGDIVP: KC; MFMOUNTSYMBOLP: 80; NUMBEROFELEMENT: 0; PCODE: P01042089220; VAL2: 100mW; FNCLASSCODEG: P01-08
U?#2 = WAKU_DEF100: PLOTTIME: HH:MM; SAVEAREA0: -56280,0,471144,298016; TIME: 20:22:11; UPDATEUSER: sptcae13; UPDATETIME: 11:35:27; SAVECOUNT: 8; OriginalSymbolOrigin: (10160,284480)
